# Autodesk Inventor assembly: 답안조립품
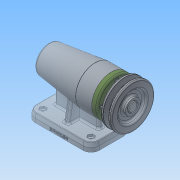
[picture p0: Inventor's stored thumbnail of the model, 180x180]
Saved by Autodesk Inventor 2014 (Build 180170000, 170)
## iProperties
Created: 2017-01
Part Number: 답안조립품
Document SubType Name: Assembly
Designer: nert
Author: nert
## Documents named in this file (11)
- C:\Users\nert\Desktop\470107V1019\답안조립품.iam
- C:\Users\nert\Desktop\470107V1019\본체.ipt
- C:\Users\nert\Desktop\470107V1019\커버.ipt
- C:\Users\nert\Desktop\470107V1019\볼트 M4 x 12.ipt
- C:\Users\nert\Desktop\470107V1019\축.ipt
- C:\Users\nert\Desktop\470107V1019\베어링 6004.ipt
- C:\Users\nert\Desktop\470107V1019\어댑터슬리브.ipt
- C:\Users\nert\Desktop\470107V1019\베어링 51202.ipt
- C:\Users\nert\Desktop\470107V1019\키 5 x 5 x 16.ipt
- C:\Users\nert\Desktop\470107V1019\V벨트풀리.ipt
- C:\Users\nert\Desktop\470107V1019\멈춤나사 M3x8.ipt
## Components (6 placed, 2 different names)
1. ISO 4762 M4 x 12:5
2. V벨트풀리:1
3. ISO 4762 M4 x 12:1
4. ISO 4762 M4 x 12:2
5. ISO 4762 M4 x 12:3
6. ISO 4762 M4 x 12:4
